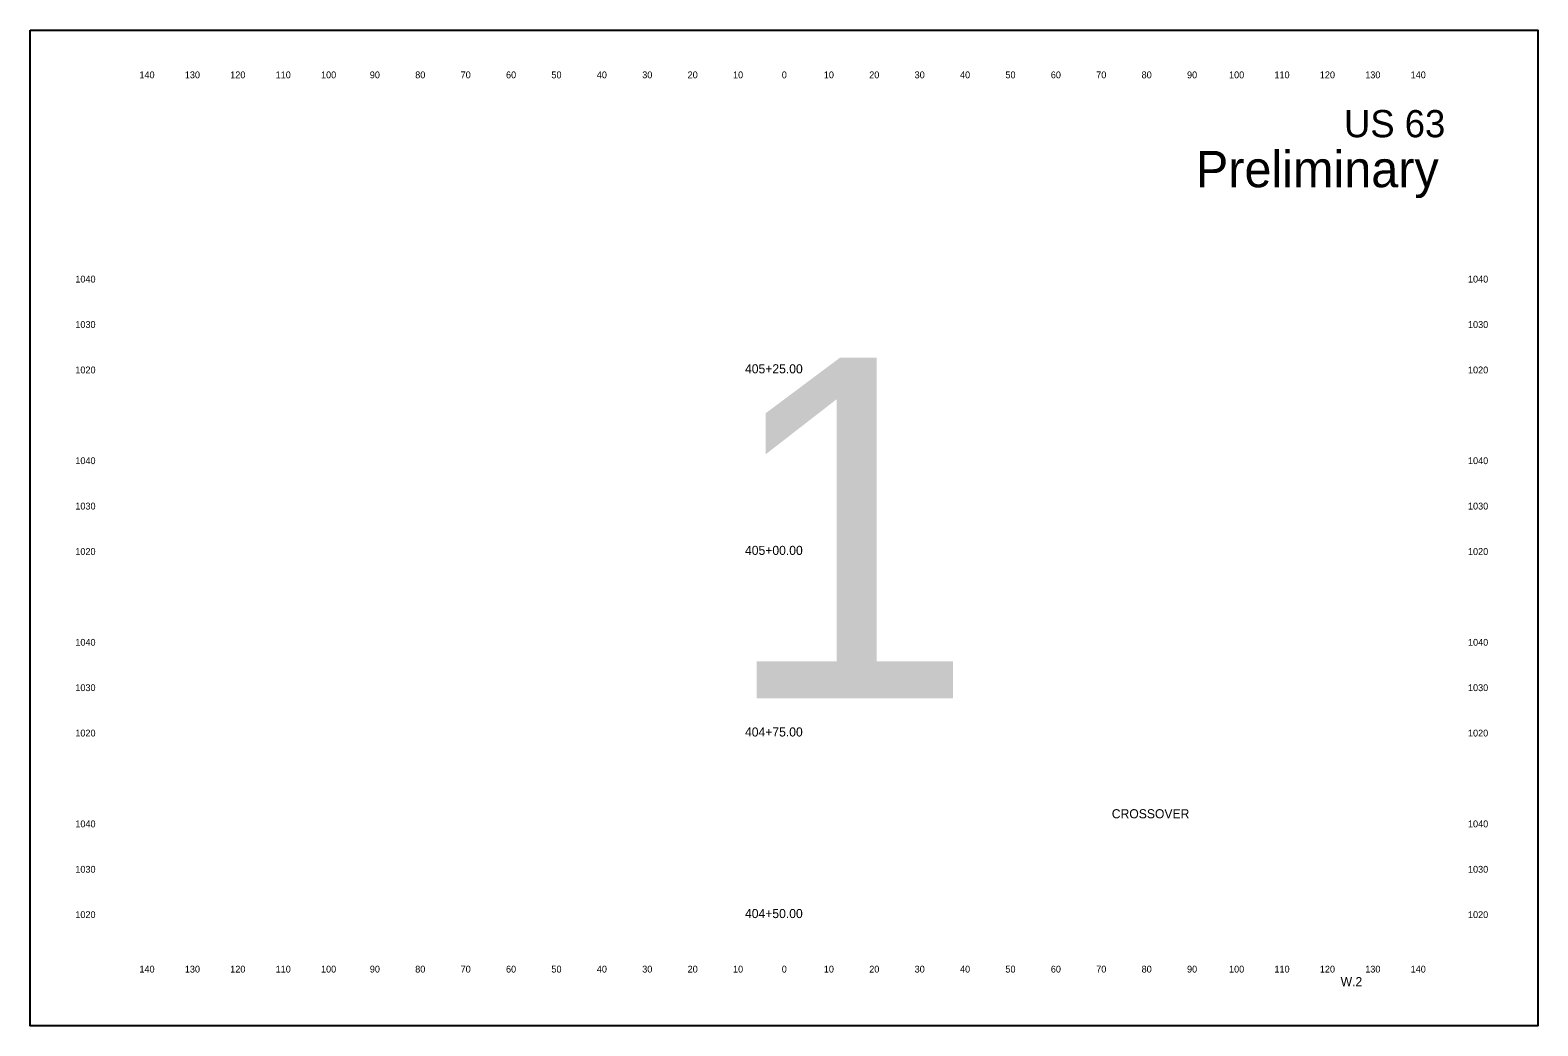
# Model space of a CAD drawing. Extents: x 10123 to 17295, y 9730 to 10181.
# Drawn here: x 10123.2 to 10455.3, y 9730.3 to 9949.6 of the extents above; entities that cross this region are included whole.
import ezdxf

# ---------------------------------------------------------------- set-up
doc = ezdxf.new("R2010")
doc.units = 0
for name, color, linetype in [('dsnTextCpn', 7, 'Continuous'), ('dsnTextCpnTitleSheetLocDesc', 7, 'Continuous'), ('dsnTextCpnTitleSheetPIN', 7, 'Continuous'), ('dsnTextCpnTitleSheetWorkType', 7, 'Continuous')]:
    doc.layers.add(name, color=color, linetype=linetype)

msp = doc.modelspace()

# ---------------------------------------------------------------- linework, layer by layer
at = {"layer": 'dsnTextCpnTitleSheetWorkType'}
msp.add_lwpolyline([(10123.21, 9949.6), (10455.29, 9949.6), (10455.29, 9730.26), (10123.21, 9730.26)], close=True, dxfattribs=at)

# ---------------------------------------------------------------- texts
at = {"layer": 'dsnTextCpn'}
for s, height, p in [('140', 1.5, (10147.27, 9939)), ('130', 1.5, (10157.27, 9939)), ('120', 1.5, (10167.27, 9939)), ('110', 1.5, (10177.27, 9939)), ('100', 1.5, (10187.27, 9939)), ('90', 1.5, (10198.02, 9939)), ('80', 1.5, (10208.02, 9939)), ('70', 1.5, (10218.02, 9939)), ('60', 1.5, (10228.02, 9939)), ('50', 1.5, (10238.02, 9939)), ('40', 1.5, (10248.02, 9939)), ('30', 1.5, (10258.02, 9939)), ('20', 1.5, (10268.02, 9939)), ('10', 1.5, (10278.02, 9939)), ('0', 1.5, (10288.76, 9939)), ('0', 1.5, (10288.76, 9939)), ('10', 1.5, (10298.02, 9939)), ('20', 1.5, (10308.02, 9939)), ('30', 1.5, (10318.02, 9939)), ('40', 1.5, (10328.02, 9939)), ('50', 1.5, (10338.02, 9939)), ('60', 1.5, (10348.02, 9939)), ('70', 1.5, (10358.02, 9939)), ('80', 1.5, (10368.02, 9939)), ('90', 1.5, (10378.02, 9939)), ('100', 1.5, (10387.27, 9939)), ('110', 1.5, (10397.27, 9939)), ('120', 1.5, (10407.27, 9939)), ('130', 1.5, (10417.27, 9939)), ('140', 1.5, (10427.27, 9939)), ('US 63', 6, (10412.6, 9926)), ('1040', 1.5, (10133.15, 9894)), ('1040', 1.5, (10439.9, 9894)), ('1030', 1.5, (10133.15, 9884)), ('1030', 1.5, (10439.9, 9884)), ('1020', 1.5, (10133.15, 9874)), ('405+25.00', 2, (10280.66, 9874)), ('1020', 1.5, (10439.9, 9874)), ('1040', 1.5, (10133.15, 9854)), ('1040', 1.5, (10439.9, 9854)), ('1030', 1.5, (10133.15, 9844)), ('1030', 1.5, (10439.9, 9844)), ('1020', 1.5, (10133.15, 9834)), ('405+00.00', 2, (10280.66, 9834)), ('1020', 1.5, (10439.9, 9834)), ('1040', 1.5, (10133.15, 9814)), ('1040', 1.5, (10439.9, 9814)), ('1030', 1.5, (10133.15, 9804)), ('1030', 1.5, (10439.9, 9804)), ('1020', 1.5, (10133.15, 9794)), ('404+75.00', 2, (10280.66, 9794)), ('1020', 1.5, (10439.9, 9794)), ('CROSSOVER', 2, (10361.45, 9775.98)), ('1040', 1.5, (10133.15, 9774)), ('1040', 1.5, (10439.9, 9774)), ('1030', 1.5, (10133.15, 9764)), ('1030', 1.5, (10439.9, 9764)), ('1020', 1.5, (10133.15, 9754)), ('404+50.00', 2, (10280.66, 9754)), ('1020', 1.5, (10439.9, 9754)), ('140', 1.5, (10147.27, 9742)), ('130', 1.5, (10157.27, 9742)), ('120', 1.5, (10167.27, 9742)), ('110', 1.5, (10177.27, 9742)), ('100', 1.5, (10187.27, 9742)), ('90', 1.5, (10198.02, 9742)), ('80', 1.5, (10208.02, 9742)), ('70', 1.5, (10218.02, 9742)), ('60', 1.5, (10228.02, 9742)), ('50', 1.5, (10238.02, 9742)), ('40', 1.5, (10248.02, 9742)), ('30', 1.5, (10258.02, 9742)), ('20', 1.5, (10268.02, 9742)), ('10', 1.5, (10278.02, 9742)), ('0', 1.5, (10288.76, 9742)), ('0', 1.5, (10288.76, 9742)), ('10', 1.5, (10298.02, 9742)), ('20', 1.5, (10308.02, 9742)), ('30', 1.5, (10318.02, 9742)), ('40', 1.5, (10328.02, 9742)), ('50', 1.5, (10338.02, 9742)), ('60', 1.5, (10348.02, 9742)), ('70', 1.5, (10358.02, 9742)), ('80', 1.5, (10368.02, 9742)), ('90', 1.5, (10378.02, 9742)), ('100', 1.5, (10387.27, 9742)), ('110', 1.5, (10397.27, 9742)), ('120', 1.5, (10407.27, 9742)), ('130', 1.5, (10417.27, 9742)), ('140', 1.5, (10427.27, 9742))]:
    msp.add_text(s, height=height, dxfattribs=at).set_placement(p)
at = {"layer": 'dsnTextCpnTitleSheetLocDesc'}
msp.add_text('Preliminary', height=8, dxfattribs=at).set_placement((10379.97, 9915))
at = {"layer": 'dsnTextCpnTitleSheetPIN'}
msp.add_text('W.2', height=2, dxfattribs=at).set_placement((10411.86, 9739))
at = {"layer": 'dsnTextCpnTitleSheetWorkType'}
msp.add_text('1', height=75, dxfattribs=at).set_placement((10275.6, 9802.43))

doc.saveas('drawing.dxf')
